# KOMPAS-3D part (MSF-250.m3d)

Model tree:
1. Ось X
2. Ось Y
3. Ось Z
4. Начало координат  (labels: Операция без истории:1)

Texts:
  Линия-выноска #1
  Линия-выноска #2
  Линия-выноска #3
  Отклонения формы и база
  Марка координационной оси
  Марка/позиционное обозначение с линией-выноской
  Марка/позиционное обозначение на линии
  Марка/позиционное обозначение без линии-выноски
